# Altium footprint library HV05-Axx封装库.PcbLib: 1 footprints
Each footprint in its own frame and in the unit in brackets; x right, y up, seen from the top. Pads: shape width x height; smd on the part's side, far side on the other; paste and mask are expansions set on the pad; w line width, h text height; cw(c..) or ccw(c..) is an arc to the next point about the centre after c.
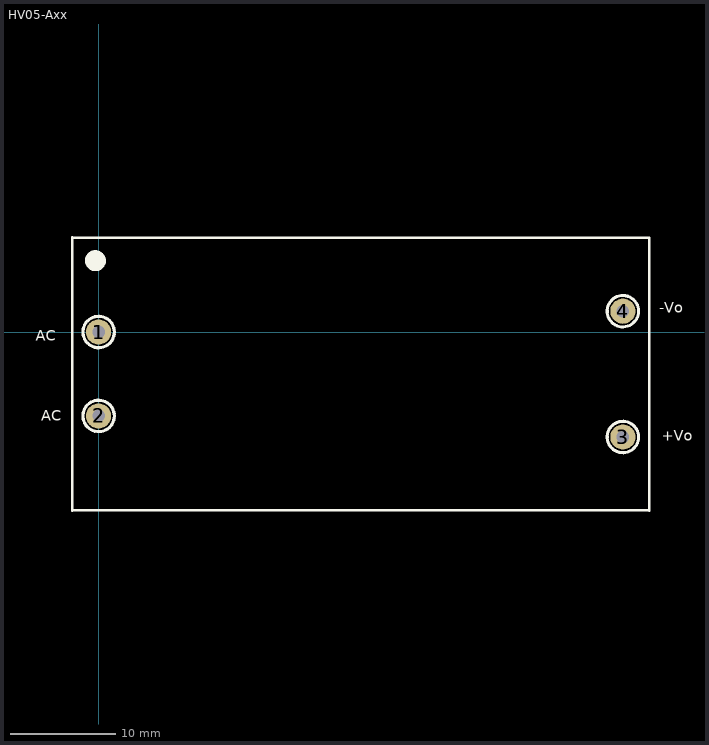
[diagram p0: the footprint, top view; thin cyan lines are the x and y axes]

## HV05-Axx [mm]
pads (8):
  round 2.4 hole 1.2: 1(0,0) 2(0,-8) 3(50,-10.011) 4(50,1.989)
  round 2.4 all layers, no hole: 1(0,0) 2(0,-8) 3(50,-10.011) 4(50,1.989)
Bottom Layer:
  lines w0.5: 50.222,1.54 50.222,2.031
Top Overlay:
  circle w0.3: c50,1.989 r1.5
  circle w0.3: c50,-10.011 r1.5
  circle w0.3: c0,-8 r1.5
  circle w0.3: c0,0 r1.5
  lines w0.254: -2.508,-17.019 52.5,-17.011 ; -2.5,-17.019 -2.508,9.016 52.5,8.988 ; 52.5,-17.019 52.5,8.997
  lines w0.99: 0.195,6.838 ccw(c-0.304,6.807) 0.196,6.807
  text "AC" at -5.988,-0.836 h1
  text "AC" at -5.48,-8.456 h1
  text "+Vo" at 53.702,-10.361 h1
  text "-Vo" at 53.448,1.831 h1
Bottom Overlay:
  circle w0.3: c0,-8 r1.5
  circle w0.3: c0,0 r1.5
  circle w0.3: c50,-10.011 r1.5
  circle w0.3: c50,1.989 r1.5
